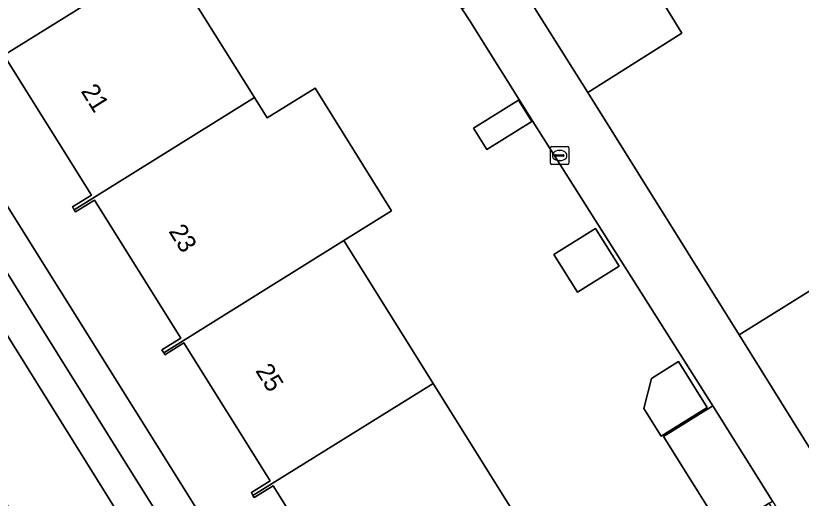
# Model space of a CAD drawing. Extents: x 158835 to 160077, y 386387 to 387778.
# Drawn here: x 159046.06 to 159089.27, y 387077.25 to 387103.8 of the extents above; entities that cross this region are included whole.
import ezdxf

# ---------------------------------------------------------------- set-up
doc = ezdxf.new("R2010")
doc.units = 0
for name, color, linetype in [('IMGEO_Erf', 7, 'Continuous'), ('IMGEO_Kolk', 7, 'Continuous'), ('IMGEO_Pand', 7, 'Continuous'), ('IMGEO_Pand_nummerreeks', 7, 'Continuous'), ('IMGEO_Parkeervlak_open', 7, 'Continuous'), ('IMGEO_Rijbaan_lokaal_open', 7, 'Continuous'), ('IMGEO_Voetpad_open', 7, 'Continuous')]:
    doc.layers.add(name, color=color, linetype=linetype)

msp = doc.modelspace()

# ---------------------------------------------------------------- linework, layer by layer
at = {"layer": 'IMGEO_Erf'}
for points in [[(159023.399, 387128.857), (159065.214, 387061.96)], [(159067.868, 387061.308), (159078.525, 387067.969), (159086.674, 387073.064), (159089.207, 387074.648), (159088.441, 387075.876), (159088.263, 387075.765), (159087.506, 387076.978), (159085.147, 387075.505), (159084.978, 387075.399), (159081.697, 387080.65), (159084.403, 387082.34), (159074.494, 387097.991), (159071.028, 387103.53), (159070.62, 387104.158), (159061.621, 387118.5)], [(159054.275, 387107.16), (159059.186, 387099.298), (159059.887, 387098.177), (159062.529, 387099.822), (159066.736, 387093.064), (159064.104, 387091.426), (159069.015, 387083.564), (159073.932, 387075.693)], [(159080.576, 387106.336), (159082.693, 387102.851), (159077.522, 387099.573), (159085.842, 387086.241), (159091.086, 387089.517), (159096.174, 387092.696), (159101.263, 387095.875), (159106.343, 387099.048), (159111.423, 387102.222), (159116.529, 387105.412)], [(159064.962, 387070.353), (159060.221, 387077.938), (159059.184, 387077.29), (159059.111, 387077.412), (159059.022, 387077.562), (159060.053, 387078.206), (159055.307, 387085.798), (159054.271, 387085.15), (159054.199, 387085.26), (159054.1, 387085.411), (159055.141, 387086.062), (159050.391, 387093.66), (159049.355, 387093.012), (159049.28, 387093.13), (159049.184, 387093.279), (159050.224, 387093.929), (159045.475, 387101.525)]]:
    msp.add_lwpolyline(points, dxfattribs=at)
for points in [[(159071.235, 387097.615), (159073.706, 387099.159), (159074.442, 387097.981), (159071.97, 387096.437)], [(159075.662, 387090.67), (159077.943, 387092.095), (159079.243, 387090.015), (159076.962, 387088.59)], [(159081.037, 387083.848), (159082.519, 387084.774), (159084.095, 387082.253), (159081.556, 387080.666), (159080.605, 387082.189)]]:
    msp.add_lwpolyline(points, close=True, dxfattribs=at)
at = {"layer": 'IMGEO_Kolk'}
for p, q in [((159075.477, 387095.684), (159075.477, 387096.536)), ((159075.552, 387096.61), (159076.404, 387096.61)), ((159075.965, 387096.39), (159075.99, 387096.39)), ((159076.478, 387096.536), (159076.478, 387095.684)), ((159075.736, 387096.104), (159075.736, 387096.116)), ((159076.174, 387096.067), (159075.776, 387096.067)), ((159075.779, 387096.153), (159076.177, 387096.153)), ((159076.22, 387096.116), (159076.22, 387096.104)), ((159076.404, 387095.61), (159075.552, 387095.61)), ((159075.988, 387095.83), (159075.963, 387095.83))]:
    msp.add_line(p, q, dxfattribs=at)
for points in [[(159075.477, 387095.684), (159075.477, 387096.536)], [(159075.552, 387096.61), (159076.404, 387096.61)], [(159076.478, 387096.536), (159076.478, 387095.684)], [(159076.404, 387095.61), (159075.552, 387095.61)]]:
    msp.add_lwpolyline(points, dxfattribs=at)
for centre, radius, start, end in [((159075.554, 387096.534), 0.0765, 91.552, 178.448), ((159075.554, 387096.534), 0.0765, 91.552, 178.448), ((159076.402, 387096.534), 0.0765, 1.552, 88.448), ((159076.402, 387096.534), 0.0765, 1.552, 88.448), ((159075.776, 387096.113), 0.0403, 85.8775, 175.7526), ((159075.773, 387096.103), 0.0366, 178.938, 274.7102), ((159076.177, 387096.11), 0.043, 264.8664, 352.4533), ((159076.181, 387096.115), 0.0386, 1.7309, 96.639), ((159075.554, 387095.686), 0.0765, 181.552, 268.448), ((159075.554, 387095.686), 0.0765, 181.552, 268.448), ((159076.402, 387095.686), 0.0765, 271.552, 358.448), ((159076.402, 387095.686), 0.0765, 271.552, 358.448)]:
    msp.add_arc(centre, radius, start, end, dxfattribs=at)
for centre, major_axis, ratio, start_param, end_param in [((159075.964, 387096.11), (-0.387, 0.002), 0.722429, 4.712389, 7.853982), ((159075.989, 387096.11), (-0.39, 0.002), 0.717154, 1.570796, 4.712389)]:
    msp.add_ellipse(centre, major_axis=major_axis, ratio=ratio, start_param=start_param, end_param=end_param, dxfattribs=at)
at = {"layer": 'IMGEO_Pand'}
for points in [[(159054.275, 387107.16), (159049.358, 387115.031), (159039.451, 387108.863), (159039.522, 387108.735), (159040.561, 387109.385), (159045.306, 387101.795), (159044.266, 387101.145), (159044.366, 387100.989)], [(159076.097, 387105.89), (159074.287, 387104.756), (159077.522, 387099.573), (159082.693, 387102.851), (159080.576, 387106.336), (159079.516, 387108.033)], [(159044.366, 387100.989), (159044.438, 387100.877), (159045.475, 387101.525), (159050.224, 387093.929), (159049.184, 387093.279), (159049.28, 387093.13), (159059.186, 387099.298), (159054.275, 387107.16)], [(159064.104, 387091.426), (159066.736, 387093.064), (159062.529, 387099.822), (159059.887, 387098.177), (159059.186, 387099.298), (159049.28, 387093.13), (159049.355, 387093.012), (159050.391, 387093.66), (159055.141, 387086.062), (159054.1, 387085.411), (159054.199, 387085.26)], [(159071.235, 387097.615), (159071.97, 387096.437), (159074.442, 387097.981), (159073.706, 387099.159)], [(159075.662, 387090.67), (159076.962, 387088.59), (159079.243, 387090.015), (159077.943, 387092.095)], [(159054.199, 387085.26), (159054.271, 387085.15), (159055.307, 387085.798), (159060.053, 387078.206), (159059.022, 387077.562), (159059.111, 387077.412), (159069.015, 387083.564), (159064.104, 387091.426)], [(159096.491, 387080.867), (159095.849, 387081.895), (159091.086, 387089.517), (159085.842, 387086.241), (159090.605, 387078.618), (159091.25, 387077.595), (159091.507, 387077.759), (159090.868, 387078.782), (159095.7, 387081.802), (159096.341, 387080.776)], [(159081.037, 387083.848), (159080.605, 387082.189), (159081.556, 387080.666), (159084.095, 387082.253), (159082.519, 387084.774)], [(159073.932, 387075.693), (159069.015, 387083.564), (159059.111, 387077.412), (159059.184, 387077.29), (159060.221, 387077.938), (159064.962, 387070.353), (159063.927, 387069.706), (159064.021, 387069.549)], [(159087.684, 387077.089), (159084.403, 387082.34), (159081.697, 387080.65), (159084.978, 387075.399), (159085.147, 387075.505), (159087.506, 387076.978)]]:
    msp.add_lwpolyline(points, close=True, dxfattribs=at)
at = {"layer": 'IMGEO_Parkeervlak_open'}
for points in [[(159042.022, 387095.318), (159040.497, 387094.367), (159041.753, 387092.354), (159051.957, 387076.019), (159060.22, 387062.853), (159062.785, 387058.895)], [(159062.903, 387061.966), (159056.85, 387071.612), (159054.854, 387074.815), (159051.799, 387079.687), (159049.806, 387082.887), (159046.941, 387087.475), (159044.952, 387090.668), (159042.022, 387095.318)]]:
    msp.add_lwpolyline(points, dxfattribs=at)
at = {"layer": 'IMGEO_Rijbaan_lokaal_open'}
msp.add_lwpolyline([(159028.658, 387103.98), (159030.654, 387100.788), (159034.686, 387094.357), (159036.688, 387091.164), (159037.331, 387090.108), (159040.565, 387084.943), (159042.564, 387081.727), (159046.674, 387075.143), (159048.667, 387071.949), (159052.636, 387065.62), (159054.64, 387062.416), (159057.409, 387057.972), (159058.484, 387056.236), (159062.785, 387058.895), (159060.22, 387062.853), (159051.957, 387076.019), (159041.753, 387092.354), (159040.497, 387094.367), (159038.554, 387097.483), (159035.596, 387102.225), (159033.587, 387105.446)], dxfattribs=at)
at = {"layer": 'IMGEO_Voetpad_open'}
for points in [[(159065.214, 387061.96), (159023.399, 387128.857)], [(159022.551, 387126.472), (159025.234, 387122.2), (159025.287, 387122.115), (159027.232, 387119.011), (159027.292, 387118.915), (159030.192, 387114.274), (159032.191, 387111.064), (159035.063, 387106.485), (159035.116, 387106.4), (159037.059, 387103.282), (159037.124, 387103.178), (159040.035, 387098.527), (159040.092, 387098.435), (159042.022, 387095.318), (159044.952, 387090.668), (159046.941, 387087.475), (159049.806, 387082.887), (159051.799, 387079.687), (159054.854, 387074.815), (159056.85, 387071.612), (159062.903, 387061.966)]]:
    msp.add_lwpolyline(points, dxfattribs=at)
msp.add_lwpolyline([(159074.287, 387104.756), (159073.536, 387105.956), (159070.62, 387104.158), (159071.028, 387103.53), (159074.494, 387097.991), (159084.403, 387082.34), (159087.684, 387077.089), (159088.441, 387075.876), (159089.207, 387074.648), (159092.005, 387076.397), (159091.25, 387077.595), (159090.605, 387078.618), (159085.842, 387086.241), (159077.522, 387099.573)], close=True, dxfattribs=at)

# ---------------------------------------------------------------- texts
at = {"layer": 'IMGEO_Pand_nummerreeks'}
for s, p in [('21', (159049.616, 387099.656)), ('23', (159054.446, 387091.941)), ('25', (159059.218, 387084.273))]:
    msp.add_text(s, height=1, rotation=302.0118, dxfattribs=at).set_placement(p)

doc.saveas('drawing.dxf')
